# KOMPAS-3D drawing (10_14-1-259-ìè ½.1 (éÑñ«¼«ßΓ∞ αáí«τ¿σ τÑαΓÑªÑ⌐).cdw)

Views: Вид 1
Referenced files in C:\Program Files\ASCON\KOMPAS-3D V10\Sys\: EngSys.lcs
Referenced files: Питание приводов.cdw
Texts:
  Текст на чертеже
  Размерные надписи
  Шероховатость
  Линия-выноска #1
  Линия-выноска #2
  Линия-выноска #3
  Отклонения формы и база
  Заголовок таблицы
  Ячейка таблицы
  Стрелка вида
  Обозначение изменения
  Фигурная скобка
  Номер узла
  Марка координационной оси
  VRCB
  Выносная надпись
  Обозначение узла
  Марка/позиционное обозначение с линией-выноской
  Марка/позиционное обозначение на линии
  Марка/позиционное обозначение без линии-выноски
  Additional DXF text style 0
  Лит-Масса-Масштаб
  Материал-Предприятие
  Обычный
  Термин
  Список определений
  Адрес
  Цитаты
  Форматированный
  Courier New
  Z-конец формы
  Z-начало формы
  Title Specification
  Body Specification ( left align )
  Body Specificaton ( centered )
  Без имени
  Normal
  heading 1
  Знак Знак Знак Знак Знак Знак
  Verdana
  Body Text
  ТекстШаг1
  Simplex
  Txt
  heading 8
  heading 3
  heading 6
  heading 7
  txt
  russ
  ООббыыччнныыйй
  ТТееррммиинн
  ССппииссоокк ооппррееддееллеенниийй
  ААддрреесс
  ЦЦииттааттыы
  ФФооррммааттиирроовваанннныыйй
  Z-ккооннеецц ффооррммыы
  Z-ннааччааллоо ффооррммыы
  Абзац Знак
  heading 2
  heading 4
  heading 5
  heading 9
  MS Sans Serif
  ГОСТ_МНЕ
  ESK - Обозначение
  Подпись в квадратике
  GOST 2.304 type A
  rustxt
  цепи
  ссылки
  Денис
  текст переноса
  табл
  Тексты. 3,2
  ЗОНА_привяз
  Body Text 3
  Title
  Маркировка
  клеммы, контакты
  тексты табл
  AGOpus
  footer
  NormalParagraphStyle
  TXT
  Definition Term
  Definition List
  Address
  Blockquote
  Preformatted
  z-Bottom of Form
  z-Top of Form
  header
  Текст 3,5
  маркировка
  Состав чартежа
  Аппараты
  подписи
  Ссылки
  ячейка табл.
  Table Contents
  Table Heading
  Tahoma
  Пояснения
  Клеммник текст
  Лист
  Ведомость рабочих чертежей комплекта 10/14-1-259-НК
  Ведомость ссылочных и прилагаемых документов
  П12-252-01 ГБ, л.1
  Ведомость рабочих чертежей комплекта 259-НК
  Профиль сетей К3, К3Н, К13
  Накопительная емкость V=10м
  Маслосборник V=100м
  Опросный лист на установку очистки поверхностных стоков
  Автоматика управления насосами.
  Схема электрическая принципиальная
  Опросный лист на резервуар для сточных вод
  (маслосборник V=100м )
  Габаритный чертеж
  Резервуар накопитель для замасленных стоков
  (накопительная емкость V=10м )
  План производственной канализации
  Прилагаемые документы
  CONTINUOUS0
  прерывистая
  POLYLINE_STYLE_0.18_RGB_0_0_0
  Стили документа
  Щит рабочего освещения
  Щит распределительный
  НКУ-22-10УЯОУ-8501
  Автоматический выключатель
  ВА63, Iном=25А
  ВА61F29-1K10+PH~220V, Iном=10А
  УЗО
  ВД63, Iном=25А
  Рубильник
  ВРА1-1-13600-00 УХЛ
  Щит аварийного освещения
  ВА61F29-1K20NA+PH-220V, Iном=20А
  ВА61F29-1K10+PH-220V, Iном=10А
  Выключатель
  Схемы щитов рабочего
  и аварийного освещения
  Ведомость эскизного проекта
  Ведомость рабочих чертежей
  комплекта 270-ЭП
  Разраб.
  Маленкин
  Галактионов
  комплекта 259-НК
  Мокин
  Н.контр.
  Ромин
  ГИП
Dimensions and other numbers on the sheet: 10/14-1-259-НК; 7; 2,5; 1,8; 2.5 курсив; 3.5; 2.5; 2,5_3; 3,2 (надписи); 3,5_01; 2,5_01; 3,5_tabl; 5_заголовок; 2,3_; 3,2_; 3,2_зона не привяз; 2,5 грязносинь; 2,5 (контакты, клеммы); 3,5; 3,2; 5; 3,2 элементы; 3,2 линия; 3,2 таблица; 3.2 маркировка; 2.5_Э5_надписи; 2.5_Э5_ссылки; 2.5_кабель; 3.2; 2.5 надписи; 3,2 (Зоны); 5,0_белый_подчёркнутый; 3.2 (текст); 3.2 фиол; 1; 10/14-1-028-НК, л.3; 10/14-1-113-КС, л.25; 10/14-1-113-КС, л.26; 10/14-1-028-НК.ОЛ1; 10/14-1-259-НК, л.2; 10/14-1-028-НК.ОЛ2; 10/14-1-028-НК.ОЛ3; 10/14-1-028-НК, л.2; 2; 8; 3; 4; 07-10-1-020-ЭП-; 11.12; 11.11; 6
